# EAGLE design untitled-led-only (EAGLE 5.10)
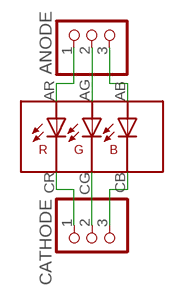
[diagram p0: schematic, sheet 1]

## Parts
ANODE  PINHD-1X3  [1X03]
CATHODE  PINHD-1X3  [1X03]
U$1  LED-RGB-SMD-HBLARGER-PADS  [LED-RGB-SMD-HB-LARGER-PADS-LARGER-GAPS]

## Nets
N$1: ANODE.1 U$1.AR
N$2: ANODE.2 U$1.AG
N$3: ANODE.3 U$1.AB
N$4: CATHODE.3 U$1.CB
N$5: CATHODE.2 U$1.CG
N$6: CATHODE.1 U$1.CR

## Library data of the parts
ANODE CATHODE = pinhead:PINHD-1X3: PIN HEADER
U$1 = trl:LED-RGB-SMD-HB

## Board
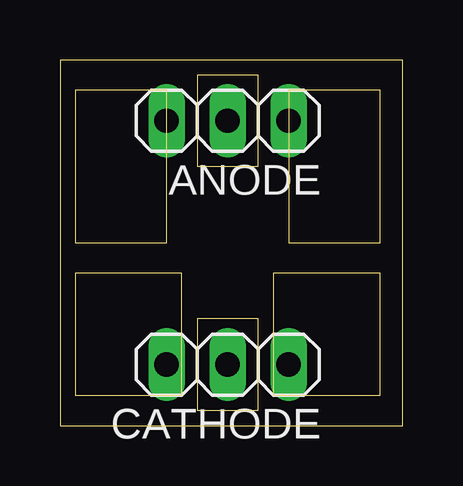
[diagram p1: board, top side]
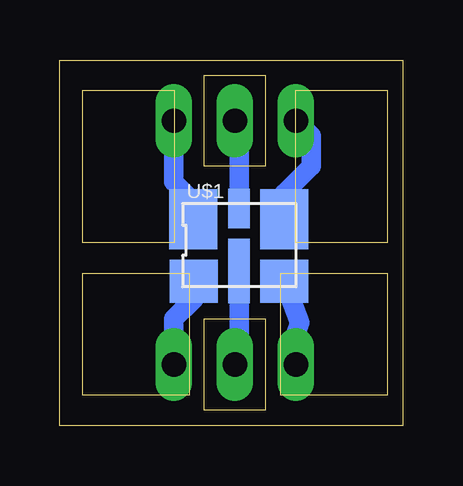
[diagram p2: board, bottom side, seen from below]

Size 14.28 x 15.23 mm. Coordinates in mm from the lower left corner, seen from the top.
Outline: 0,0 14.28,0 14.28,15.23 0,15.23 0,0
Copper layers (1*16): Top 0.035mm / dielectric 1.5mm / Bottom 0.035mm
Design rules "default": minimum track width 10mil, minimum drill 24mil, track to track 8mil, track to pad 8mil, pad to pad 8mil, via to via 8mil, smd to smd 8mil, copper to edge 40mil, drill to drill 8mil, minimum pad ring 10mil, minimum via ring 8mil, stop-mask expansion 4mil, vias tented up to drill 0mil, thermal gap 10mil
Milling: area 9.5,7.6 to 13.3,14; area 8.9,1.3 to 13.3,6.3; area 5.7,10.8 to 8.3,14.6; area 5.7,0.6 to 8.3,4.4; area 0.6,7.6 to 4.4,14; area 0.6,1.3 to 5.1,6.3

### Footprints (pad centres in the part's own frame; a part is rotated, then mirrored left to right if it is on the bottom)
1X03 = drill 1.016 long: 1 -2.54,0; 2 0,0; 3 2.54,0
LED-RGB-SMD-HB-LARGER-PADS-LARGER-GAPS = smd 2 x 2.5: AB 2.05,0.98; AR -1.73,0.98 | smd 0.9 x 1.65: AG 0.17,1.42 | smd 2 x 1.8: CB 2.06,-1.61; CR -1.72,-1.61 | smd 0.9 x 2.7: CG 0.17,-1.18

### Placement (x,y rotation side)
ANODE  6.99,12.7 180 top
CATHODE  6.99,2.54 180 top
U$1  6.99,7.62 0 bottom

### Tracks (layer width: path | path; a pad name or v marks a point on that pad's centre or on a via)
N$1
  Bottom 0.813: U$1.AR 8.71,9.35 9.53,10.16 ANODE.1
N$2
  Bottom 0.813: U$1.AG 6.82,12.53 ANODE.2
N$3
  Bottom 0.813: U$1.AB 4.93,9.67 3.81,10.79 3.81,12.06 ANODE.3
N$4
  Bottom 0.813: U$1.CB 4.29,4.29 4.45,3.81 CATHODE.3
N$5
  Bottom 0.813: U$1.CG 6.82,2.71 CATHODE.2
N$6
  Bottom 0.813: U$1.CR 8.71,5.26 9.53,4.45 CATHODE.1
